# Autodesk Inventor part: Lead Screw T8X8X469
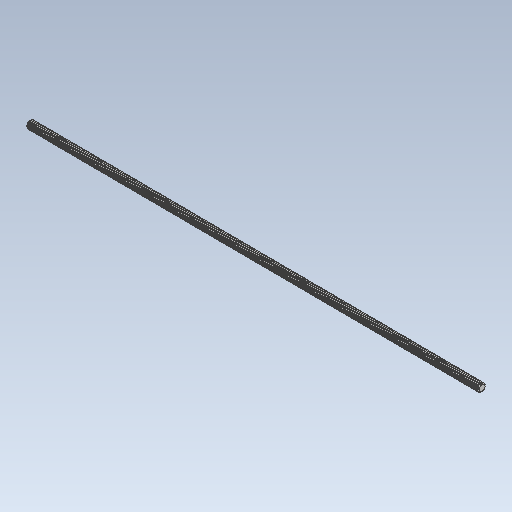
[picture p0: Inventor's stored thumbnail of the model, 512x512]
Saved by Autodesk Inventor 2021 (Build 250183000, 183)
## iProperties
Created: 2026-10
Part Number: Lead Screw T8X8X469
Material: Steel
Document SubType Name: Modeling
Designer: hp
Density: 7.85 g/cm^3
Appearance: Default
Author: hp
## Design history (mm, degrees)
feature "Body1"
body "Solid1"
